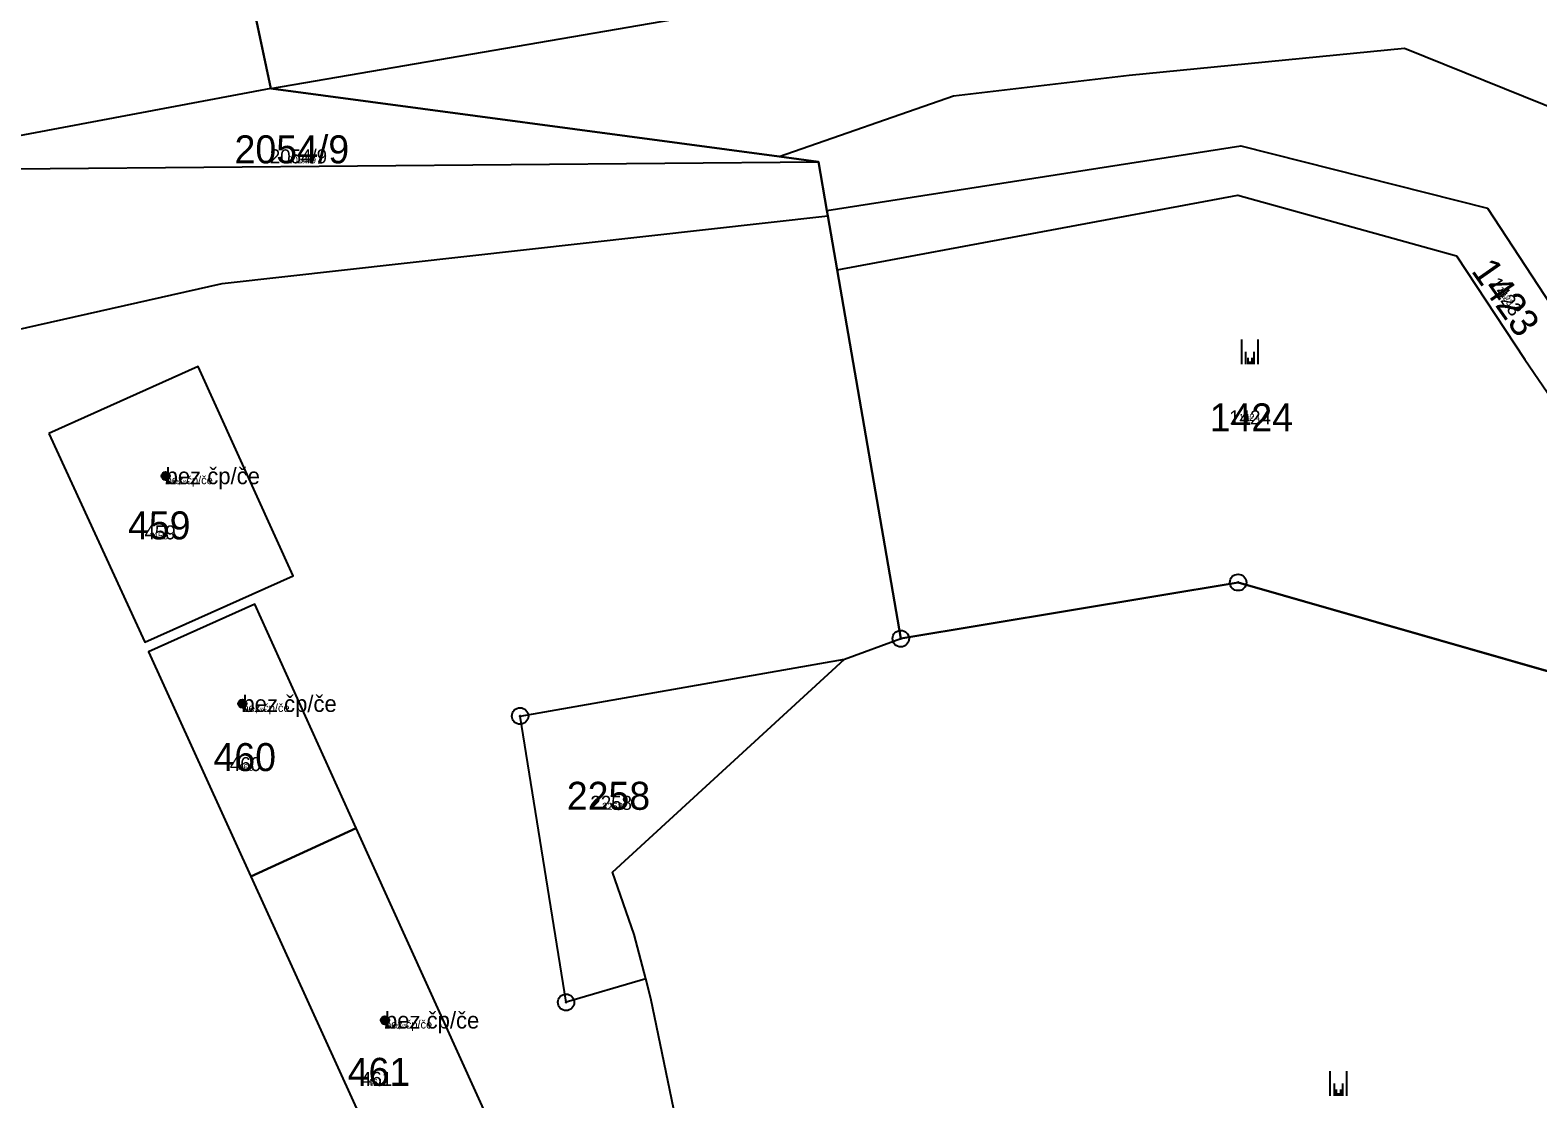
# Model space of a CAD drawing. Extents: x -744652 to -739090, y -980828 to -975855.
# Drawn here: x -741846.2 to -741754.7, y -978898.7 to -978833.9 of the extents above; entities that cross this region are included whole.
import ezdxf

# ---------------------------------------------------------------- set-up
doc = ezdxf.new("R2010")
doc.units = 0
for name, color, linetype in [('KAT_01_hranice KU', 7, 'Continuous'), ('KAT_02_hranice parcel', 7, 'Continuous'), ('KAT_03_1000_st čísla parcelní', 7, 'Continuous'), ('KAT_03_1000_čísla parcelní', 7, 'Continuous'), ('KAT_03_1000_čísla popisná', 7, 'Continuous'), ('KAT_03_100_st čísla parcelní', 7, 'Continuous'), ('KAT_03_100_čísla parcelní', 7, 'Continuous'), ('KAT_03_100_čísla popisná', 7, 'Continuous'), ('KAT_03_250_st čísla parcelní', 7, 'Continuous'), ('KAT_03_250_čísla parcelní', 7, 'Continuous'), ('KAT_03_250_čísla popisná', 7, 'Continuous'), ('KAT_03_500_st čísla parcelní', 7, 'Continuous'), ('KAT_03_500_čísla parcelní', 7, 'Continuous'), ('KAT_03_500_čísla popisná', 7, 'Continuous'), ('KAT_05_1000_značky kultur', 7, 'Continuous'), ('KAT_05_100_značky kultur', 7, 'Continuous'), ('KAT_05_250_značky kultur', 7, 'Continuous'), ('KAT_05_500_značky kultur', 7, 'Continuous'), ('KAT_07_1000_značky budov', 7, 'Continuous'), ('KAT_07_100_značky budov', 7, 'Continuous'), ('KAT_07_500_značky budov', 7, 'Continuous'), ('KAT_11_značky bodu BP', 7, 'Continuous'), ('KAT_14_plocha_budovy', 7, 'Continuous')]:
    doc.layers.add(name, color=color, linetype=linetype)

msp = doc.modelspace()

# ---------------------------------------------------------------- linework, layer by layer
at = {"layer": 'KAT_01_hranice KU'}
msp.add_lwpolyline([(-741798.65, -978597.08), (-741808.54, -978644.45), (-741817.44, -978673.77), (-741828.59, -978738.33), (-741829.25, -978742.15), (-741829.42, -978745.8), (-741834.68, -978797.61), (-741835.56, -978818.63), (-741834.39, -978818.59), (-741833.13, -978829.98), (-741831.56, -978837.44), (-741800.71, -978841.57), (-741798.32, -978841.89), (-741797.81, -978844.85), (-741797.75, -978845.17), (-741797.19, -978848.44), (-741793.33, -978870.82), (-741772.86, -978867.41), (-741736.53, -978877.84), (-741709.02, -978891.15), (-741724.37, -978911.25)], dxfattribs=at)
at = {"layer": 'KAT_02_hranice parcel'}
for p, q in [((-741831.56, -978837.44), (-741833.13, -978829.98)), ((-741831.56, -978837.44), (-741833.13, -978829.98)), ((-741831.56, -978837.44), (-741885.83, -978847.62)), ((-741800.71, -978841.57), (-741831.56, -978837.44)), ((-741800.71, -978841.57), (-741831.56, -978837.44)), ((-741798.32, -978841.89), (-741800.71, -978841.57)), ((-741798.32, -978841.89), (-741800.71, -978841.57)), ((-741797.81, -978844.85), (-741798.32, -978841.89)), ((-741797.81, -978844.85), (-741798.32, -978841.89)), ((-741797.75, -978845.17), (-741797.81, -978844.85)), ((-741797.75, -978845.17), (-741797.81, -978844.85)), ((-741797.19, -978848.44), (-741797.75, -978845.17)), ((-741797.19, -978848.44), (-741797.75, -978845.17)), ((-741793.33, -978870.82), (-741797.19, -978848.44)), ((-741793.33, -978870.82), (-741797.19, -978848.44)), ((-741772.86, -978867.41), (-741793.33, -978870.82)), ((-741772.86, -978867.41), (-741793.33, -978870.82)), ((-741736.53, -978877.84), (-741772.86, -978867.41)), ((-741736.53, -978877.84), (-741772.86, -978867.41)), ((-741796.74, -978872.07), (-741793.33, -978870.82)), ((-741832.77, -978885.25), (-741826.37, -978882.32))]:
    msp.add_line(p, q, dxfattribs=at)
for points in [[(-741831.56, -978837.44), (-741780.77, -978828.69), (-741774.92, -978827.57), (-741768.67, -978827.36), (-741762.67, -978827.93), (-741756.75, -978829.17), (-741751.07, -978831.13), (-741745.75, -978833.78), (-741726.34, -978844.96)], [(-741800.71, -978841.57), (-741790.14, -978837.89), (-741779.47, -978836.63), (-741762.77, -978835), (-741742.25, -978843.26), (-741730.06, -978851.44), (-741721.24, -978857.86), (-741715.23, -978862.29)], [(-741797.81, -978844.85), (-741772.69, -978840.92), (-741757.72, -978844.7), (-741753.11, -978851.73), (-741744.47, -978865.32), (-741737.87, -978871.86), (-741714.3, -978883.95), (-741698.83, -978893.72)], [(-741861.97, -978846.91), (-741854.3, -978842.37), (-741798.32, -978841.89)], [(-741797.19, -978848.44), (-741772.87, -978843.91), (-741759.62, -978847.6), (-741755.46, -978853.89), (-741745.94, -978867.81), (-741738.68, -978874.58), (-741736.53, -978877.84)], [(-741857.21, -978857.22), (-741853.12, -978853.46), (-741834.5, -978849.28), (-741797.75, -978845.17)], [(-741845.03, -978858.37), (-741839.2, -978871.04), (-741830.2, -978867.01), (-741835.97, -978854.3), (-741845.03, -978858.37)], [(-741826.37, -978882.32), (-741832.53, -978868.74), (-741838.98, -978871.63), (-741832.77, -978885.25)], [(-741808.8, -978891.47), (-741813.64, -978892.89), (-741816.43, -978875.52), (-741796.74, -978872.07)], [(-741808.8, -978891.47), (-741809.51, -978888.77), (-741810.82, -978884.99), (-741796.74, -978872.07)], [(-741832.77, -978885.25), (-741822.21, -978908.43), (-741815.86, -978905.5), (-741826.37, -978882.32)], [(-741806.3, -978915.42), (-741806.47, -978904.4), (-741806.88, -978900.46), (-741808.49, -978892.66), (-741808.8, -978891.47)]]:
    msp.add_lwpolyline(points, dxfattribs=at)
at = {"layer": 'KAT_03_1000_čísla popisná'}
for centre in [(-741837.94, -978860.95), (-741837.94, -978860.95), (-741833.28, -978874.77), (-741833.28, -978874.77), (-741824.63, -978893.98), (-741824.63, -978893.98)]:
    msp.add_circle(centre, 0.25, dxfattribs=at)
at = {"layer": 'KAT_03_100_čísla popisná'}
for centre in [(-741837.94, -978860.95), (-741837.94, -978860.95), (-741833.28, -978874.77), (-741833.28, -978874.77), (-741824.63, -978893.98), (-741824.63, -978893.98)]:
    msp.add_circle(centre, 0.025, dxfattribs=at)
at = {"layer": 'KAT_03_250_čísla popisná'}
for centre in [(-741837.94, -978860.95), (-741837.94, -978860.95), (-741833.28, -978874.77), (-741833.28, -978874.77), (-741824.63, -978893.98), (-741824.63, -978893.98)]:
    msp.add_circle(centre, 0.0625, dxfattribs=at)
at = {"layer": 'KAT_03_500_čísla popisná'}
for centre in [(-741837.94, -978860.95), (-741837.94, -978860.95), (-741833.28, -978874.77), (-741833.28, -978874.77), (-741824.63, -978893.98), (-741824.63, -978893.98)]:
    msp.add_circle(centre, 0.125, dxfattribs=at)
at = {"layer": 'KAT_05_1000_značky kultur'}
for p, q in [((-741772.641, -978854.16), (-741772.641, -978852.66)), ((-741771.64, -978854.16), (-741771.64, -978852.66)), ((-741767.271, -978898.56), (-741767.271, -978897.06)), ((-741766.27, -978898.56), (-741766.27, -978897.06))]:
    msp.add_line(p, q, dxfattribs=at)
at = {"layer": 'KAT_05_100_značky kultur'}
for p, q in [((-741772.181, -978854.16), (-741772.181, -978854.01)), ((-741772.081, -978854.16), (-741772.081, -978854.01)), ((-741766.811, -978898.56), (-741766.811, -978898.41)), ((-741766.711, -978898.56), (-741766.711, -978898.41))]:
    msp.add_line(p, q, dxfattribs=at)
at = {"layer": 'KAT_05_250_značky kultur'}
for p, q in [((-741772.258, -978854.16), (-741772.258, -978853.785)), ((-741772.008, -978854.16), (-741772.008, -978853.785)), ((-741766.888, -978898.56), (-741766.888, -978898.185)), ((-741766.638, -978898.56), (-741766.638, -978898.185))]:
    msp.add_line(p, q, dxfattribs=at)
at = {"layer": 'KAT_05_500_značky kultur'}
for p, q in [((-741772.385, -978854.16), (-741772.385, -978853.41)), ((-741771.885, -978854.16), (-741771.885, -978853.41)), ((-741767.015, -978898.56), (-741767.015, -978897.81)), ((-741766.515, -978898.56), (-741766.515, -978897.81))]:
    msp.add_line(p, q, dxfattribs=at)
at = {"layer": 'KAT_07_1000_značky budov'}
for centre in [(-741837.947, -978860.949), (-741833.287, -978874.769), (-741824.637, -978893.979)]:
    msp.add_circle(centre, 0.175, dxfattribs=at)
at = {"layer": 'KAT_07_100_značky budov'}
for centre in [(-741837.941, -978860.95), (-741833.281, -978874.77), (-741824.631, -978893.98)]:
    msp.add_circle(centre, 0.0175, dxfattribs=at)
at = {"layer": 'KAT_07_500_značky budov'}
for centre, radius in [((-741837.943, -978860.95), 0.0875), ((-741837.942, -978860.95), 0.0438), ((-741833.283, -978874.77), 0.0875), ((-741833.282, -978874.77), 0.0438), ((-741824.633, -978893.98), 0.0875), ((-741824.632, -978893.98), 0.0438)]:
    msp.add_circle(centre, radius, dxfattribs=at)
at = {"layer": 'KAT_11_značky bodu BP'}
for centre, radius in [((-741772.86, -978867.41), 0.5), ((-741772.86, -978867.41), 0.0303), ((-741793.33, -978870.82), 0.5), ((-741793.33, -978870.82), 0.0303), ((-741816.43, -978875.52), 0.5), ((-741816.43, -978875.52), 0.0303), ((-741813.64, -978892.89), 0.5), ((-741813.64, -978892.89), 0.0303)]:
    msp.add_circle(centre, radius, dxfattribs=at)
at = {"layer": 'KAT_14_plocha_budovy'}
for points in [[(-741845.03, -978858.37), (-741839.2, -978871.04), (-741830.2, -978867.01), (-741835.97, -978854.3)], [(-741832.53, -978868.74), (-741838.98, -978871.63), (-741832.77, -978885.25), (-741826.37, -978882.32)], [(-741826.37, -978882.32), (-741832.77, -978885.25), (-741822.21, -978908.43), (-741815.86, -978905.5)]]:
    msp.add_lwpolyline(points, close=True, dxfattribs=at)

# ---------------------------------------------------------------- texts
at = {"layer": 'KAT_03_1000_st čísla parcelní'}
for s, p in [('459', (-741840.224, -978864.8)), ('460', (-741835.034, -978878.86)), ('461', (-741826.894, -978897.96))]:
    msp.add_text(s, height=1.7, dxfattribs=at).set_placement(p)
at = {"layer": 'KAT_03_1000_čísla parcelní'}
for s, p in [('2054/9', (-741833.755, -978841.98)), ('1424', (-741774.587, -978858.246)), ('2258', (-741813.597, -978881.21))]:
    msp.add_text(s, height=1.7, dxfattribs=at).set_placement(p)
msp.add_text('1423', height=1.7, rotation=305, dxfattribs=at).set_placement((-741758.758, -978848.508))
at = {"layer": 'KAT_03_1000_čísla popisná'}
for s, height, p in [('bez čp/če', 1, (-741837.94, -978861.45)), ('459', 0.017, (-741838.243, -978864.8)), ('bez čp/če', 1, (-741833.28, -978875.27)), ('460', 0.017, (-741833.073, -978878.86)), ('bez čp/če', 1, (-741824.63, -978894.48)), ('461', 0.017, (-741825.304, -978897.96))]:
    msp.add_text(s, height=height, dxfattribs=at).set_placement(p)
at = {"layer": 'KAT_03_100_st čísla parcelní'}
for s, p in [('459', (-741838.423, -978864.8)), ('460', (-741833.251, -978878.86)), ('461', (-741825.449, -978897.96))]:
    msp.add_text(s, height=0.17, dxfattribs=at).set_placement(p)
at = {"layer": 'KAT_03_100_čísla parcelní'}
for s, p in [('2054/9', (-741829.912, -978841.98)), ('1424', (-741772.455, -978857.481)), ('2258', (-741811.025, -978881.21))]:
    msp.add_text(s, height=0.17, dxfattribs=at).set_placement(p)
msp.add_text('1423', height=0.17, rotation=305, dxfattribs=at).set_placement((-741756.863, -978849.88))
at = {"layer": 'KAT_03_100_čísla popisná'}
for s, height, p in [('bez čp/če', 0.1, (-741837.94, -978861.45)), ('459', 0.0017, (-741838.225, -978864.8)), ('bez čp/če', 0.1, (-741833.28, -978875.27)), ('460', 0.0017, (-741833.055, -978878.86)), ('bez čp/če', 0.1, (-741824.63, -978894.48)), ('461', 0.0017, (-741825.29, -978897.96))]:
    msp.add_text(s, height=height, dxfattribs=at).set_placement(p)
at = {"layer": 'KAT_03_250_st čísla parcelní'}
for s, p in [('459', (-741838.723, -978864.8)), ('460', (-741833.548, -978878.86)), ('461', (-741825.689, -978897.96))]:
    msp.add_text(s, height=0.425, dxfattribs=at).set_placement(p)
at = {"layer": 'KAT_03_250_čísla parcelní'}
for s, p in [('2054/9', (-741830.553, -978841.98)), ('1424', (-741772.81, -978857.609)), ('2258', (-741811.454, -978881.21))]:
    msp.add_text(s, height=0.425, dxfattribs=at).set_placement(p)
msp.add_text('1423', height=0.425, rotation=305, dxfattribs=at).set_placement((-741757.179, -978849.651))
at = {"layer": 'KAT_03_250_čísla popisná'}
for s, height, p in [('bez čp/če', 0.25, (-741837.94, -978861.45)), ('459', 0.00425, (-741838.228, -978864.8)), ('bez čp/če', 0.25, (-741833.28, -978875.27)), ('460', 0.00425, (-741833.058, -978878.86)), ('bez čp/če', 0.25, (-741824.63, -978894.48)), ('461', 0.00425, (-741825.292, -978897.96))]:
    msp.add_text(s, height=height, dxfattribs=at).set_placement(p)
at = {"layer": 'KAT_03_500_st čísla parcelní'}
for s, p in [('459', (-741839.223, -978864.8)), ('460', (-741834.044, -978878.86)), ('461', (-741826.091, -978897.96))]:
    msp.add_text(s, height=0.85, dxfattribs=at).set_placement(p)
at = {"layer": 'KAT_03_500_čísla parcelní'}
for s, p in [('2054/9', (-741831.62, -978841.98)), ('1424', (-741773.402, -978857.821)), ('2258', (-741812.168, -978881.21))]:
    msp.add_text(s, height=0.85, dxfattribs=at).set_placement(p)
msp.add_text('1423', height=0.85, rotation=305, dxfattribs=at).set_placement((-741757.705, -978849.27))
at = {"layer": 'KAT_03_500_čísla popisná'}
for s, height, p in [('bez čp/če', 0.5, (-741837.94, -978861.45)), ('459', 0.0085, (-741838.233, -978864.8)), ('bez čp/če', 0.5, (-741833.28, -978875.27)), ('460', 0.0085, (-741833.063, -978878.86)), ('bez čp/če', 0.5, (-741824.63, -978894.48)), ('461', 0.0085, (-741825.296, -978897.96))]:
    msp.add_text(s, height=height, dxfattribs=at).set_placement(p)

doc.saveas('drawing.dxf')
